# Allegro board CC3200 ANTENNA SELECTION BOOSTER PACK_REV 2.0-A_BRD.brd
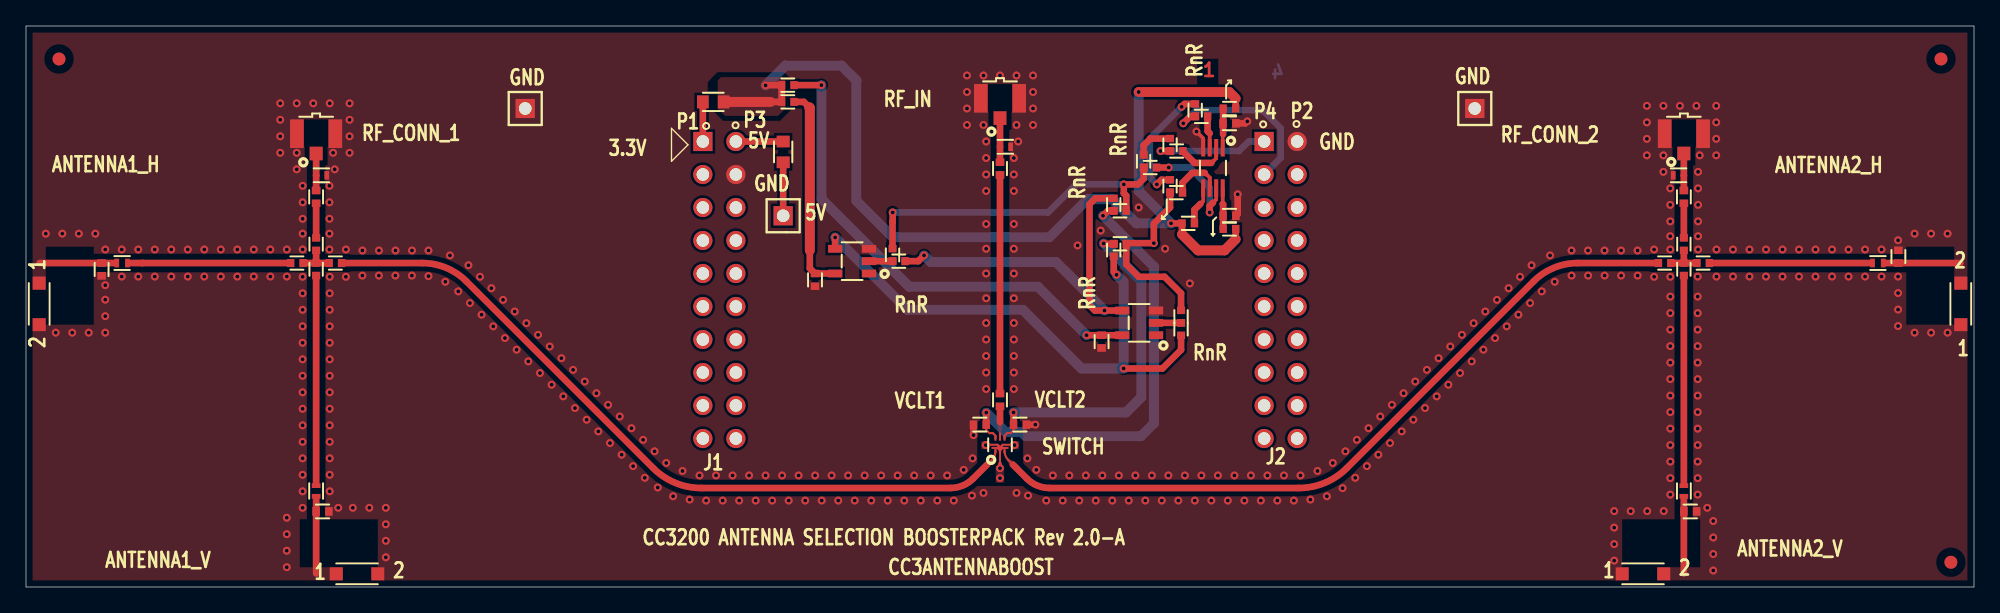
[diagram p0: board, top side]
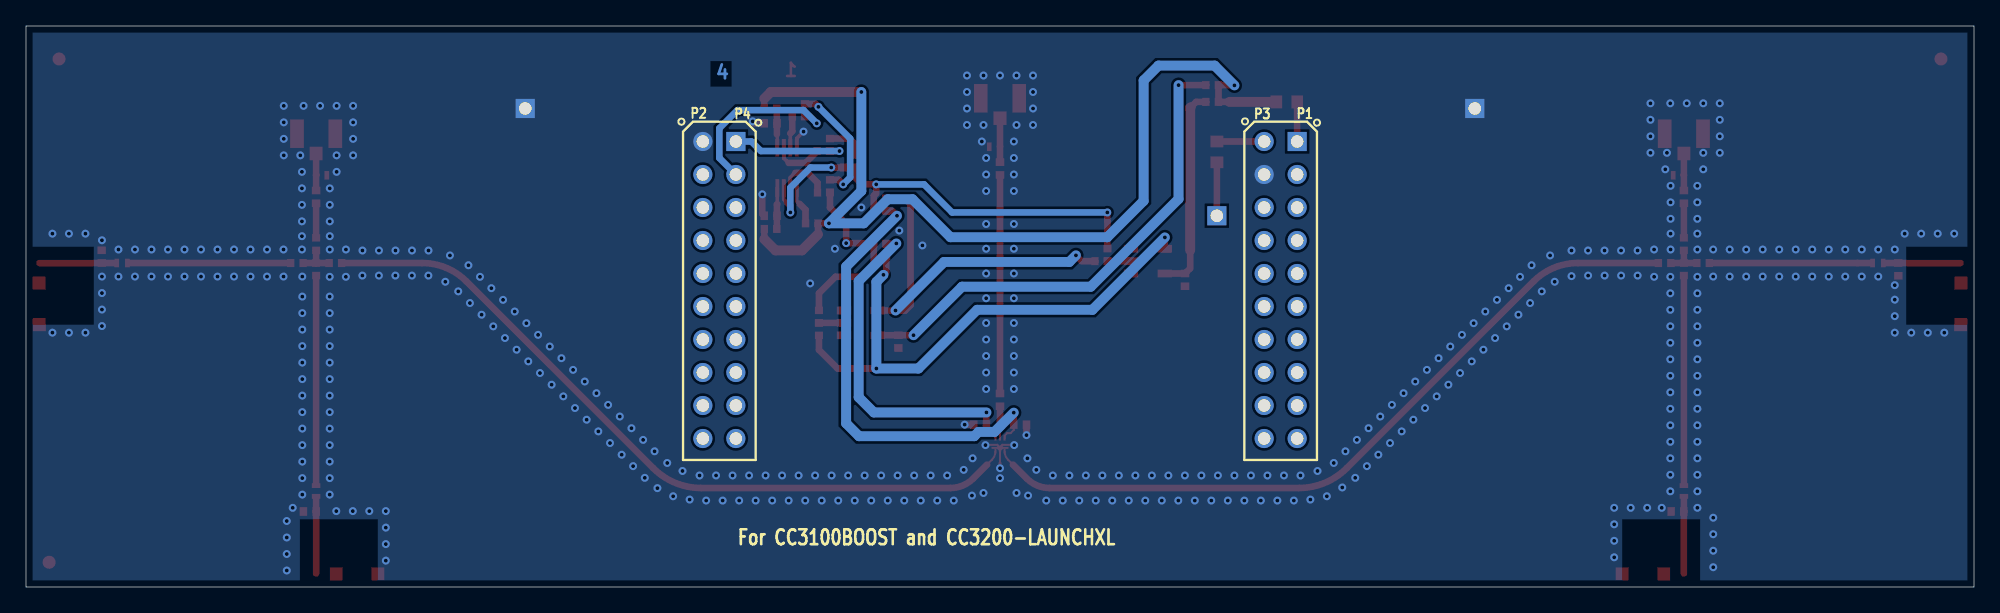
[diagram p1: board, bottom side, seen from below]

Outline 149.86 x 43.18 mm; copper layers: TOP, GND, PWR, BOTTOM. Coordinates in mm from the lower left corner of the outline.
Outline path: 0,43.18 149.86,43.18 149.86,0 0,0 0,43.18

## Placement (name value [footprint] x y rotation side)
C33  100pF  [CC0402]  22.32 30.03 90 top
C34  1pF  [CC0402]  22.81 5.82 180 top
C35  100pF  [CC0402]  127.54 30.03 90 top
C36  1pF  [CC0402]  128.03 5.82 180 top
C37  10pF  [CC0402]  74.93 32.21 90 top
C38  100pF  [CC0402]  74.93 14.4 90 top
C39  33pF  [CC0402]  76.46 12.5 0 top
C40  33pF  [CC0402]  73.38 12.5 180 top
C42  1pF  [CC0402]  144.04 25.43 270 top
C44  1pF  [CC0402]  5.82 24.45 90 top
C45  1uF  [CC0402]  60.7 23.64 270 top
C46  1uF  [CC0402]  82.75 18.89 270 top
C47  0.1uF  [CC0402]  92.58 35.69 0 top
C48  0.1uF  [CC0402]  92.58 28.57 0 top
E1  2.45GHz Ant  [ANT_AH316M]  25.47 1.02 0 top
E2  2.45GHz Ant  [ANT_AH316M]  124.39 1.02 0 top
E4  2.45GHz Ant  [ANT_AH316M]  148.84 21.79 90 top
E6  2.45GHz Ant  [ANT_AH316M]  1.02 21.79 270 top
J1  CONN_RCPT_10x2  [HDR_THVT_2X10_100_F]  52.07 34.29 180 bottom
J2  CONN_RCPT_10x2  [HDR_THVT_2X10_100_F]  95.25 34.29 180 bottom
J17  CONN_U.FL  [EMERSON_128-0711-201]  22.32 34.89 0 top
J18  CONN_U.FL  [EMERSON_128-0711-201]  127.54 34.89 0 top
J19  CONN_U.FL  [EMERSON_128-0711-201]  74.93 37.61 0 top
L7  NC  [INDC_0402CS]  22.73 31.69 180 top
L10  3.6nH  [INDC_0402CS]  22.32 7.39 270 top
L11  3.6nH  [INDC_0402CS]  127.54 7.39 270 top
L12  NC  [INDC_0402CS]  127.13 31.69 0 top
L13  NC  [INDC_0402CS]  75.34 33.88 180 top
L15  3.6nH  [INDC_0402CS]  142.47 24.94 0 top
L17  3.6nH  [INDC_0402CS]  7.39 24.94 180 top
NOREF  -  []  49.53 0 90 top
NOREF#2  -  []  23.79 34.89 0 top
NOREF#3  -  [unnamed#2]  147.32 40.64 0 top
NOREF#4  -  [unnamed#2]  148.08 1.91 0 top
NOREF#5  -  [unnamed#2]  2.54 40.64 0 top
NOREF#6  -  []  0 43.18 0 top
NOREF#7  -  []  27.07 1.02 0 top
R44  NC  [RC0402]  22.32 26.39 270 top
R45  0 R  [RC0402]  22.32 24.46 270 top
R46  NC  [RC0402]  127.54 26.39 270 top
R47  0 R  [RC0402]  127.54 24.46 270 top
R50  NC  [RC0402]  20.84 24.94 180 top
R59  RES0603  [RC0603]  52.87 37.34 180 top
R60  RES0603  [RC0603]  58.25 33.49 90 top
R62  0 R  [RC0402]  23.8 24.94 180 top
R64  0 R  [RC0402]  126.06 24.94 0 top
R73  0 R  [RC0402]  58.61 38.63 180 top
R74  0 R  [RC0402]  58.61 37.34 180 top
R76  NC  [RC0402]  129.02 24.94 0 top
R79  0 R  [RC0402]  89.41 27.99 0 top
R80  0 R  [RC0402]  92.58 36.83 0 top
R81  0 R  [RC0402]  92.58 27.56 0 top
R82  0 R  [RC0402]  88.52 33.56 180 top
R83  NC  [RC0402]  88.01 34.04 270 top
R85  NC  [RC0402]  89.94 36.7 270 top
R86  0 R  [RC0402]  90.42 36.22 0 top
R88  0 R  [RC0402]  86.49 32.29 180 top
R89  NC  [RC0402]  85.98 32.77 90 top
R90  0 R  [RC0402]  88.49 30.35 180 top
R91  NC  [RC0402]  88.01 30.86 90 top
R92  0 R  [RC0402]  84.16 28.96 0 top
R93  0 R  [RC0402]  84.16 26.42 0 top
R94  NC  [RC0402]  83.68 29.44 90 top
R95  NC  [RC0402]  83.68 25.94 90 top
R96  NC  [RC0402]  66.66 25.56 270 top
R97  NC  [RC0402]  67.14 25.08 0 top
R98  NC  [RC0402]  88.86 19.85 90 top
R99  NC  [RC0402]  88.86 20.81 90 top
TP9  TP THRU  [HDR_THVT_1X1_100_M]  58.25 28.57 0 top
TP10  TP THRU  [HDR_THVT_1X1_100_M]  111.46 36.83 0 top
TP11  TP THRU  [HDR_THVT_1X1_100_M]  38.4 36.83 0 top
U1  SWITCH  [SW_SKY13351-378LF]  74.93 10.95 90 top
U4  SN74AVCH2T45DCUR  [SOP50P310X90-8]  91.31 32.26 270 top
U6  INVERTER  [SOT23-5]  63.55 25.08 180 top
U7  INVERTER  [SOT23-5]  85.63 20.33 180 top

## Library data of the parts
C33-C40 C42 C44-C48 = CAP
E1 E2 E4 E6 = CHIP_ANTENNA_2T
J1 J2 = CONN_RCPT_10X2
J17-J19 = CONN_UFL_3P
L7 L10-L13 L15 L17 = INDUCTOR
R44-R47 R50 R62 R64 R73 R74 R76 R79-R83 R85 R86 R88-R99 = RESISTOR
R59 R60 = RES0603
TP9-TP11 = TEST_POINT_THRU
U1 = SWITCH
U4 = SN74AVCH2T45
U6 U7 = INVERTER

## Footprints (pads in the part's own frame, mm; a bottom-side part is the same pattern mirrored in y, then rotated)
ANT_AH316M
  rect 1x1 smd: 1(-1.6,0) 2(1.6,0)
CC0402
  rect 0.58x0.66 smd: 1(-0.49,0) 2(0.49,0)
EMERSON_128-0711-201
  rect 1x1.05 smd: 1(0,-1.525)
  rect 1.05x2.2 smd: 2A(-1.475,0) 2B(1.475,0)
HDR_THVT_1X1_100_M
  rect 1.473x1.473 hole 0.965: 1(0,0)
HDR_THVT_2X10_100_F
  rect 1.473x1.473 hole 0.965: 1(0,0)
  round 1.473 hole 0.965: 2(-2.54,0) 3(0,-2.54) 4(-2.54,-2.54) 5(0,-5.08) 6(-2.54,-5.08) 7(0,-7.62) 8(-2.54,-7.62) 9(0,-10.16) 10(-2.54,-10.16) 11(0,-12.7) 12(-2.54,-12.7) 13(0,-15.24) 14(-2.54,-15.24) 15(0,-17.78) 16(-2.54,-17.78) 17(0,-20.32) 18(-2.54,-20.32) 19(0,-22.86) 20(-2.54,-22.86)
INDC_0402CS
  rect 0.36x0.66 smd: 1(-0.41,0) 2(0.41,0)
RC0402
  rect 0.57x0.62 smd: 1(-0.48,0) 2(0.48,0)
RC0603
  rect 0.9x1 smd: 1(-0.8,0) 2(0.8,0)
SOP50P310X90-8
  rect 1.346x0.305 smd: 1(-1.55,0.75) 2(-1.55,0.25) 3(-1.55,-0.25) 4(-1.55,-0.75) 5(1.55,-0.75) 6(1.55,-0.25) 7(1.55,0.25) 8(1.55,0.75)
SOT23-5
  rect 1.1x0.6 smd: 1(-1.3,0.95) 2(-1.3,0) 3(-1.3,-0.95) 4(1.3,-0.95) 5(1.3,0.95)
SW_SKY13351-378LF
  rect 0.33x0.15 smd: 1(-0.485,0.35) 3(-0.485,-0.35) 4(0.485,-0.35) 5(0.485,0) 6(0.485,0.35)
  custom 0.196x0.196 smd: 2(-0.5,0)
unnamed#2
  round 1 smd: (0,0)

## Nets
GND: C34.1 C34.2 C36.1 C36.2 C39.2 C40.2 C42.1 C42.2 C44.1 C44.2 C45.2 C46.2 C47.2 C48.2 E1.1(FEED) E1.2 E2.1(FEED) E2.2 E4.1(FEED) E4.2 E6.1(FEED) E6.2 J1.4 J2.2 J17.2A(GND1) J17.2B(GND2) J18.2A(GND1) J18.2B(GND2) J19.2A(GND1) J19.2B(GND2) L7.1 L10.2 L11.2 L12.1 L13.1 L15.2 L17.2 TP10.1 TP11.1 U1.2(GND) U4.4(GND) U6.3(GND) U7.3(GND)
VCC_3V3: R59.1 R73.2 R74.2 R79.1 R80.2 R81.2
VCC_3V3_GPIO26: C45.1 R74.1 U6.5(VCC)
VCC_3V3_GPIO27: C46.1 R73.1 U7.5(VCC)
VCC_5V: J1.2 R60.2
GPIO26: J2.1 R82.2 R83.2
GPIO27: J2.3 R85.2 R86.1
VCTL1: C40.1 R92.1 R94.1 U1.6(VCTL1)
VCTL2: C39.1 R93.1 R95.2 U1.4(VCTL2)
N192262: J1.1 R59.2
N192340: R60.1 TP9.1
N199868: R44.2 R45.1 R50.1 R62.2
N199876: R62.1 U1.1(OUT1)
N199888: R64.1 U1.3(OUT2)
N199912: C38.1 U1.5(IN)
N200476: C37.2 J19.1(CENTER) L13.2
N200512: C37.1 C38.2
N201883: L10.1 R45.2
N202698: C33.2 J17.1(CENTER) L7.2
N202732: C33.1 R44.1
N202976: L17.1 R50.2
N204722: R46.2 R47.1 R64.2 R76.1
N204850: L11.1 R47.2
N204918: C35.2 J18.1(CENTER) L12.2
N204956: C35.1 R46.1
N204984: L15.1 R76.2
N222165: C47.1 R80.1 U4.1(VCCA)
N222453: R88.1 U4.7(B1)
N222461: R90.1 U4.6(B2)
N222517: C48.1 R81.1 U4.8(VCCB)
N223645: R86.2 U4.3(A2)
N225569: R83.1 R89.2
N225701: R88.2 R89.1 R92.2 R96.1
N229561: R82.1 U4.2(A1)
N229933: R85.1 R91.2
N229937: R90.2 R91.1 R93.2 R99.2
N231294: R94.2 R97.2 U7.4(OUT)
N231312: R95.1 R98.1 U6.4(OUT)
N231358: R98.2 R99.1 U7.2(IN)
N231374: R96.2 R97.1 U6.2(IN)
N231796: R79.2 U4.5(DIR)

Pads without a net: J1 3 5 6 7 8 9 10 11 12 13 14 15 16 17 18 19 20; J2 4 5 6 7 8 9 10 11 12 13 14 15 16 17 18 19 20; U6 1; U7 1

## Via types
v1: diameter 0.61, hole 0.305, TOP to BOTTOM, 451 vias

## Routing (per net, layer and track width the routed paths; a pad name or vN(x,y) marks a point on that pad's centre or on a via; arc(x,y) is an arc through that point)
GND: length 33.7
  TOP w0.152: 74.93,9.88 74.93,9.65 ; 74.93,9.88 74.93,9.88 74.93,9.65 ; 74.93,9.88 U1.2 74.93,10.74 ; 74.93,9.65 74.93,9.65 ; 74.93,9.65 74.93,9.53 74.93,9.53 74.93,9.65 ; v1(73.84,10.92) 73.86,10.95 74.75,10.95 74.93,10.77 74.93,10.74 ; v1(76.05,10.92) 76.02,10.95 75.13,10.95 74.93,10.74
  TOP w0.203: L17.2 6.87,24.94 ; L15.2 143.02,24.94 ; L11.2 127.54,6.86 ; L10.2 22.32,6.89
  TOP w0.254: v1(74.93,9.14) 74.93,9.53
  TOP w0.279: U4.4 90.56,34.53 v1(90.04,35.05)
  TOP w0.505: v1(93.22,30.23) 93.22,28.72 C48.2 ; C47.2 93.8,35.69 v1(93.95,35.84)
  TOP w0.508: 143.02,24.94 C42.2 148.82,24.94 ; 22.32,1.04 C34.2 22.32,6.89 ; 6.87,24.94 C44.2 1.04,24.94 ; 127.54,1.04 C36.2 127.54,6.86 ; v1(77.65,12.5) 77.65,12.5 C39.2 ; C40.2 v1(72.89,11.69)
  vias: v1(1.52,27.2) v1(2.29,19.58) v1(2.79,27.2) v1(3.56,19.58) v1(4.06,27.2) v1(4.83,19.58) v1(5.33,27.2) v1(6.1,25.98) v1(6.1,23.23) v1(6.1,22.12) v1(6.1,20.85) v1(6.1,19.58) v1(7.37,25.98) v1(7.37,23.89) v1(8.64,25.98) v1(8.64,23.89) v1(9.91,25.98) v1(9.91,23.89) v1(11.18,25.98) v1(11.18,23.89) v1(12.45,25.98) v1(12.45,23.89) v1(13.72,25.98) v1(13.72,23.89) v1(14.99,25.98) v1(14.99,23.89) v1(16.26,25.98) v1(16.26,23.89) v1(17.53,25.98) v1(17.53,23.89) v1(18.8,25.98) v1(18.8,23.89) v1(19.56,37.23) v1(19.56,35.96) v1(19.56,34.69) v1(19.56,33.42) v1(20.07,25.98) v1(20.07,23.89) v1(20.06,5.33) v1(20.06,4.06) v1(20.06,2.79) v1(20.06,1.52) v1(20.83,37.23) v1(20.83,33.42) v1(20.83,32.15) v1(21.29,30.88) v1(21.29,29.61) v1(21.29,28.34) v1(21.29,27.2) v1(21.29,25.98) v1(21.28,23.88) v1(21.28,22.61) v1(21.28,21.34) v1(21.28,20.07) v1(21.28,18.8) v1(21.28,17.53) v1(21.28,16.26) v1(21.28,14.99) v1(21.28,13.72) v1(21.28,12.45) v1(21.28,11.18) v1(21.28,9.91) v1(21.28,8.64) v1(21.28,7.37) v1(21.28,6.1) v1(22.1,37.23) v1(23.34,30.88) v1(23.34,29.61) v1(23.34,28.34) v1(23.34,27.2) v1(23.34,25.98) v1(23.37,37.23) v1(23.36,23.88) v1(23.36,22.61) v1(23.36,21.34) v1(23.36,20.07) v1(23.36,18.8) v1(23.36,17.53) v1(23.36,16.26) v1(23.36,14.99) v1(23.36,13.72) v1(23.36,12.45) v1(23.36,11.18) v1(23.36,9.91) v1(23.36,8.64) v1(23.36,7.37) v1(23.62,33.42) v1(23.75,32.15) v1(24.02,6.1) v1(24.61,25.98) v1(24.61,23.88) v1(24.89,37.23) v1(24.89,35.96) v1(24.89,34.69) v1(24.89,33.42) v1(25.14,6.1) v1(25.88,25.9) v1(25.88,23.97) v1(26.41,6.1) v1(27.15,23.97) v1(27.15,25.9) v1(27.68,6.1) v1(27.68,4.83) v1(27.68,3.56) v1(27.68,2.29) v1(28.42,25.9) v1(28.42,23.97) v1(29.69,25.9) v1(29.69,23.97) v1(30.96,25.9) v1(30.96,23.93) v1(32.26,23.5) v1(32.61,25.52) v1(33.25,22.75) v1(34.04,24.77) v1(34.15,21.86) v1(34.92,23.88) v1(35.05,20.96) v1(35.8,23) v1(35.95,20.06) v1(36.7,22.1) v1(36.84,19.16) v1(37.6,21.2) v1(37.74,18.26) v1(38.5,20.31) v1(38.64,17.37) v1(39.39,19.41) v1(39.54,16.47) v1(40.29,18.51) v1(40.44,15.57) v1(41.19,17.61) v1(41.33,14.67) v1(42.09,16.71) v1(42.23,13.77) v1(42.99,15.82) v1(43.13,12.88) v1(43.88,14.92) v1(44.03,11.98) v1(44.78,14.02) v1(44.93,11.08) v1(45.68,13.12) v1(45.82,10.18) v1(46.58,12.22) v1(46.7,9.3) v1(47.48,11.33) v1(47.6,8.4) v1(48.36,10.45) v1(48.6,7.66) v1(49.25,9.55) v1(49.78,6.99) v1(50.51,8.93) v1(51.05,6.73) v1(51.82,8.59) v1(52.32,6.65) v1(53.09,8.59) v1(53.59,6.65) v1(54.36,8.59) v1(54.86,6.65) v1(55.63,8.59) v1(56.13,6.65) v1(56.9,8.59) v1(57.4,6.65) v1(58.17,8.59) v1(58.67,6.65) v1(59.44,8.59) v1(59.94,6.65) v1(60.71,8.59) v1(61.21,6.65) v1(61.98,8.59) v1(62.48,6.65) v1(63.25,8.59) v1(63.75,6.65) v1(64.52,8.59) v1(65.02,6.65) v1(65.79,8.59) v1(66.29,6.65) v1(67.06,8.59) v1(67.56,6.65) v1(68.33,8.59) v1(68.83,6.65) v1(69.6,8.59) v1(70.1,6.65) v1(70.87,8.59) v1(71.37,6.65) v1(72.14,9.02) v1(72.39,39.37) v1(72.39,38.1) v1(72.39,36.83) v1(72.39,35.56) v1(72.82,9.91) v1(72.77,7.04) v1(73.66,39.37) v1(73.66,35.56) v1(73.66,7.24) v1(73.86,34.29) v1(73.86,33.02) v1(73.86,31.75) v1(73.86,30.48) v1(73.86,27.94) v1(73.86,26.04) v1(73.86,24.13) v1(73.86,22.23) v1(73.86,20.32) v1(73.86,19.05) v1(73.86,17.78) v1(73.86,16.51) v1(73.86,15.24) v1(74.93,39.37) v1(74.93,8.38) v1(76,33.02) v1(76,31.75) v1(76,30.48) v1(76,27.94) v1(76,26.04) v1(76,24.13) v1(76,22.23) v1(76,20.32) v1(76,19.05) v1(76,17.78) v1(76,16.51) v1(76,15.24) v1(76.2,39.37) v1(76.2,35.56) v1(76.2,7.24) v1(76.33,34.29) v1(77.04,9.91) v1(77.09,7.04) v1(77.47,39.37) v1(77.47,38.1) v1(77.47,36.83) v1(77.47,35.56) v1(77.72,9.02) v1(78.49,6.65) v1(78.99,8.59) v1(79.76,6.65) v1(80.26,8.59) v1(80.9,26.29) v1(81.03,6.65) v1(81.53,8.59) v1(82.3,6.65) v1(82.68,27.43) v1(82.8,8.59) v1(83.57,6.65) v1(84.07,8.59) v1(84.84,6.65) v1(85.34,8.59) v1(85.6,29.21) v1(86.11,6.65) v1(86.61,8.59) v1(87.38,6.65) v1(87.63,26.04) v1(87.88,8.59) v1(88.65,6.65) v1(89.15,8.59) v1(89.53,23.37) v1(89.92,6.65) v1(90.42,8.59) v1(91.19,6.65) v1(91.69,8.59) v1(92.46,6.65) v1(92.96,8.59) v1(93.73,6.65) v1(94.23,8.59) v1(95,6.65) v1(95.5,8.59) v1(96.27,6.65) v1(96.77,8.59) v1(97.54,6.65) v1(98.04,8.59) v1(98.81,6.73) v1(99.35,8.93) v1(100.08,6.99) v1(100.53,9.55) v1(101.28,7.61) v1(101.5,10.45) v1(102.26,8.4) v1(102.38,11.33) v1(103.16,9.3) v1(103.28,12.22) v1(104.04,10.18) v1(104.18,13.12) v1(104.93,11.08) v1(105.08,14.02) v1(105.83,11.98) v1(105.98,14.92) v1(106.73,12.88) v1(106.87,15.82) v1(107.63,13.77) v1(107.77,16.71) v1(108.53,14.67) v1(108.67,17.61) v1(109.42,15.57) v1(109.57,18.51) v1(110.32,16.47) v1(110.47,19.41) v1(111.22,17.37) v1(111.36,20.31) v1(112.12,18.26) v1(112.26,21.2) v1(113.02,19.16) v1(113.16,22.1) v1(113.91,20.06) v1(114.06,23) v1(114.81,20.96) v1(114.94,23.88) v1(115.71,21.86) v1(115.82,24.77) v1(116.61,22.75) v1(117.25,25.52) v1(117.6,23.5) v1(118.9,25.9) v1(118.9,23.97) v1(120.17,25.9) v1(120.17,23.97) v1(121.44,25.9) v1(121.44,23.97) v1(122.18,5.84) v1(122.18,4.57) v1(122.18,3.3) v1(122.18,2.03) v1(122.71,25.9) v1(122.71,23.97) v1(123.45,5.84) v1(123.98,25.9) v1(123.98,23.97) v1(124.7,37.03) v1(124.7,35.76) v1(124.7,34.49) v1(124.7,33.22) v1(124.72,5.84) v1(125.25,25.98) v1(125.25,23.88) v1(125.97,37.03) v1(125.97,33.22) v1(125.97,31.95) v1(125.99,5.84) v1(126.49,30.68) v1(126.49,29.41) v1(126.49,28.14) v1(126.49,27) v1(126.49,25.98) v1(126.5,23.88) v1(126.5,22.35) v1(126.5,21.08) v1(126.5,19.81) v1(126.5,18.54) v1(126.5,17.27) v1(126.5,16) v1(126.5,14.73) v1(126.5,13.46) v1(126.5,12.19) v1(126.5,10.92) v1(126.5,9.65) v1(126.5,8.38) v1(126.5,7.11) v1(127.24,37.03) v1(128.51,37.03) v1(128.63,31.95) v1(128.63,30.68) v1(128.63,29.41) v1(128.63,28.14) v1(128.63,27) v1(128.63,25.98) v1(128.61,23.89) v1(128.61,22.35) v1(128.61,21.08) v1(128.61,19.81) v1(128.61,18.54) v1(128.61,17.27) v1(128.61,16) v1(128.61,14.73) v1(128.61,13.46) v1(128.61,12.19) v1(128.61,10.92) v1(128.61,9.65) v1(128.61,8.38) v1(128.61,7.11) v1(128.76,33.22) v1(129.34,6.1) v1(129.8,5.08) v1(129.8,3.81) v1(129.8,2.54) v1(129.8,1.27) v1(130.03,37.03) v1(130.03,35.76) v1(130.03,34.49) v1(130.03,33.22) v1(130.05,25.98) v1(130.05,23.89) v1(131.32,25.98) v1(131.32,23.89) v1(132.59,25.98) v1(132.59,23.89) v1(133.86,25.98) v1(133.86,23.89) v1(135.13,25.98) v1(135.13,23.89) v1(136.4,25.98) v1(136.4,23.89) v1(137.67,25.98) v1(137.67,23.89) v1(138.94,25.98) v1(138.94,23.89) v1(140.21,25.98) v1(140.21,23.89) v1(141.48,25.98) v1(141.48,23.89) v1(142.75,25.98) v1(142.75,23.89) v1(144.02,26.69) v1(144.02,23.89) v1(144.02,22.62) v1(144.02,21.35) v1(144.02,20.08) v1(145.29,27.2) v1(145.29,19.58) v1(146.56,27.2) v1(146.56,19.58) v1(147.83,27.2) v1(147.83,19.58)
VCC_3V3: length 78.8
  TOP w0.505: R73.2 56.88,38.63 v1(56.9,38.61) ; 88.93,27.15 R79.1 v1(88.09,27.99) ; R81.2 93.06,26.77 ; R80.2 93.06,37.6
  TOP w0.508: 57.28,37.34 R74.2 R73.2
  TOP w0.762: 88.93,27.15 90.17,25.91 92.2,25.91 93.06,26.77 ; 57.28,37.34 R59.1 ; 93.06,37.6 92.56,38.1 v1(85.6,38.1)
  BOTTOM w0.762: v1(85.6,38.1) 85.6,30.48 v1(88.09,27.99) 85.42,27.99 83.57,29.84 81.66,29.84 78.74,26.92 66.67,26.92 63.88,29.72 63.88,38.99 62.74,40.13 58.42,40.13 v1(56.9,38.61)
VCC_3V3_GPIO26: length 15.9
  TOP w0.505: 60.3,25.91 60.3,24.53 C45.1 U6.5 ; R74.1 59.84,37.34 60.24,36.94
  TOP w0.762: 60.3,25.91 60.3,36.88 60.24,36.94
VCC_3V3_GPIO27: length 38.4
  TOP w0.505: U7.5 C46.1 v1(81.58,19.38) ; R73.1 v1(61.19,38.63)
  BOTTOM w0.762: v1(81.58,19.38) 77.85,23.11 67.94,23.11 61.19,29.87 v1(61.19,38.63)
VCC_5V: length 3.6
  TOP w0.505: R60.2 J1.2
GPIO26: length 9
  TOP w0.508: R82.2 R83.2 v1(87.28,33.56)
  BOTTOM w0.505: J2.1 94.06,34.29 93.32,33.56 v1(87.28,33.56)
GPIO27: length 13.7
  TOP w0.505: v1(89.03,35.69) 89.56,36.22 R85.2
  BOTTOM w0.505: v1(89.03,35.69) 90.04,36.7 95.12,36.7 96.52,35.31 96.52,33.02 J2.3
VCTL1: length 35.1
  TOP w0.152: C40.1 73.87,12.08 74.11,11.84 74.38,11.84 74.58,11.64 U1.6
  TOP w0.505: R92.1 83.24,28.96 v1(82.85,28.57)
  TOP w0.508: C40.1 v1(73.87,13.42)
  BOTTOM w0.762: v1(73.87,13.42) 75.35,11.94 76.58,11.94 76.91,11.61 85.78,11.61 86.77,12.6 86.77,24.66 v1(82.85,28.57)
VCTL2: length 26.6
  TOP w0.152: U1.4 75.28,11.64 75.48,11.84 75.75,11.84 75.97,12.07 C39.1
  TOP w0.505: v1(82.91,26.44) 82.93,26.42 R93.1
  TOP w0.508: C39.1 v1(75.97,13.44)
  BOTTOM w0.762: v1(82.91,26.44) 85.8,23.55 85.8,14.61 84.63,13.44 v1(75.97,13.44)
N192262: length 3
  TOP w0.505: R59.2 J1.1
N192340: length 4.1
  TOP w0.505: TP9.1 R60.1
N199868: length 3
  TOP w0.508: R45.1 R50.1 ; R45.1 R62.2 ; R45.1 R44.2
N199876: length 58.3
  TOP w0.152: 73.94,9.42 74.3,9.78 arc(74.51,10.09) U1.1
  TOP w0.508: R62.1 30.48,24.94 arc(32.32,24.57) 33.87,23.53 48.26,9.14 arc(49.95,8.02) 51.94,7.62 71.12,7.62 arc(72.06,7.81) 72.85,8.34 73.94,9.42
N199888: length 58.3
  TOP w0.152: 75.92,9.42 75.56,9.78 arc(75.35,10.09) U1.3
  TOP w0.508: R64.1 119.38,24.94 arc(117.54,24.57) 115.99,23.53 101.6,9.14 arc(99.91,8.02) 97.92,7.62 78.74,7.62 arc(77.8,7.81) 77.01,8.34 75.92,9.42
N199912: length 1.6
  TOP w0.152: U1.5 74.93,11.82 74.93,11.83
  TOP w0.508: 74.93,12.7 C38.1
N200476: length 3.4
  TOP w0.508: C37.2 L13.2 J19.1
N200512: length 16.8
  TOP w0.508: C38.2 C37.1
N201883: length 16.2
  TOP w0.203: L10.1 22.32,7.9
  TOP w0.508: 22.32,7.9 R45.2
N202698: length 2.9
  TOP w0.508: J17.1 L7.2 C33.2
N202732: length 2.7
  TOP w0.508: C33.1 R44.1
N202976: length 12.6
  TOP w0.203: L17.1 7.94,24.94
  TOP w0.508: R50.2 8.95,24.94 7.94,24.94
N204722: length 3
  TOP w0.508: R47.1 R64.2 ; R47.1 R46.2 ; R47.1 R76.1
N204850: length 16.2
  TOP w0.203: L11.1 127.54,7.95
  TOP w0.508: 127.54,7.95 R47.2
N204918: length 2.9
  TOP w0.508: J18.1 L12.2 C35.2
N204956: length 2.7
  TOP w0.508: R46.1 C35.1
N204984: length 12.6
  TOP w0.203: L15.1 141.92,24.94
  TOP w0.508: 141.92,24.94 R76.2
N222165: length 3
  TOP w0.254: 92.09,34.84 92.06,34.81 U4.1
  TOP w0.505: 92.09,34.84 C47.1 92.09,36.82 R80.1
N222453: length 8.7
  TOP w0.279: 91.31,29.58 91.56,29.83 U4.7
  TOP w0.505: R88.1 v1(87.91,32.29) ; 91.31,29.58 91.06,29.32 v1(91.06,28.83)
  BOTTOM w0.505: v1(87.91,32.29) 89.51,32.29 91.06,30.73 v1(91.06,28.83)
N222461: length 4.1
  TOP w0.279: U4.6 91.06,31.49 91.06,31.5 91.06,31.52 90.86,31.72 90.83,31.72 90.68,31.88
  TOP w0.505: R90.1 88.97,31.12 89.73,31.88 90.68,31.88
N222517: length 3.2
  TOP w0.279: 92.06,29.48 U4.8
  TOP w0.505: 92.06,29.48 92.09,29.45 C48.1 92.09,27.57 R81.1
N223645: length 2.5
  TOP w0.279: 91.06,34.92 U4.3
  TOP w0.505: R86.2 90.9,35.08 91.06,34.92
N225569: length 3
  TOP w0.508: R83.1 86.51,34.52 85.98,33.99 R89.2
N225701: length 26.1
  TOP w0.505: v1(66.67,28.83) 66.67,28.14 66.66,28.13 R96.1 ; R92.2 84.64,30.12 84.45,30.3 v1(84.45,30.99) 85.54,30.99 85.98,31.43 R89.1
  BOTTOM w0.505: v1(66.67,28.83) 78.61,28.83 80.77,30.99 v1(84.45,30.99)
N229561: length 3.9
  TOP w0.203: 89,33.53 R82.1
  TOP w0.279: 91.19,32.64 91.34,32.79 91.36,32.79 91.56,32.99 91.56,33.01 91.56,33.02 U4.2
  TOP w0.505: 89,33.53 89.89,32.64 91.19,32.64
N229933: length 9.5
  TOP w0.505: R91.2 87.35,31.34 v1(87,30.99) ; R85.1 89.13,37.18 v1(88.9,36.96)
  BOTTOM w0.505: v1(87,30.99) 86.46,31.53 86.46,34.51 v1(88.9,36.96)
N229937: length 14.6
  TOP w0.505: R91.1 R90.2 88.01,29.21 86.77,27.97 v1(86.77,26.47) 84.69,26.47 R93.2 84.64,24.83 85.6,23.88 87.59,23.88 88.86,22.61 R99.2
N231294: length 29.8
  TOP w0.505: v1(69.09,25.53) 68.64,25.08 R97.2 ; R94.2 82.27,29.92 81.81,29.46 81.81,21.69 82.22,21.28 v1(82.97,21.28) U7.4
  BOTTOM w0.762: v1(69.09,25.53) 69.6,25.02 79.23,25.02 v1(82.97,21.28)
N231312: length 42.3
  TOP w0.505: R95.1 83.68,24.24 v1(83.9,24.03) ; U6.4 62.25,26.04 v1(62.25,26.91) ; v1(84.44,16.82) 87.42,16.82 88.86,18.25 R98.1
  BOTTOM w0.762: v1(83.9,24.03) 84.44,23.48 v1(84.44,16.82) 81.2,16.82 76.69,21.34 67.82,21.34 v1(62.25,26.91)
N231358: length 1.9
  TOP w0.505: R98.2 U7.2
N231374: length 1.8
  TOP w0.505: U6.2 R97.1
N231796: length 3
  TOP w0.279: 90.35,29.49 90.35,29.5 90.56,29.69 U4.5
  TOP w0.505: 90.35,29.49 89.89,29.03 R79.2

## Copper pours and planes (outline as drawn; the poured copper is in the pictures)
GND on TOP: 19,0.51 0.51,0.51 0.51,17.63 0.51,28.45 0.51,42.67 149.35,42.67 149.35,27.05 149.35,18.72 149.35,0.51 129.54,0.51 120.29,0.51 29.72,0.51 ; 10 cut-outs
GND on BOTTOM: 0.51,0.51 0.51,17.63 0.51,20.19 5.22,20.19 5.22,26.19 0.51,26.19 0.51,42.67 149.35,42.67 149.35,27.86 149.35,26.19 144.64,26.19 144.64,20.19 149.35,20.19 149.35,0.51 129.54,0.51 128.79,0.51 128.79,5.22 122.79,5.22 122.79,0.51 29.72,0.51 27.07,0.51 27.07,5.22 21.07,5.22 21.07,0.51
GND on GND, PWR: 19,0.51 0.51,0.51 0.51,17.63 0.51,28.45 0.51,42.67 149.35,42.67 149.35,27.86 149.35,18.72 149.35,0.51 129.54,0.51 120.29,0.51 29.72,0.51
VCC_3V3 on TOP: 57.85,36.26 58.42,36.83 58.42,38.99 58.17,39.24 53.47,39.24 53.21,38.99 53.21,36.83 53.78,36.26
N199876 on TOP: 74.32,9.92 74.32,9.92 74.43,9.83 74.43,9.8 74.14,9.28 74.04,9.17 73.73,8.85 73.37,9.2 73.78,9.61
N199888 on TOP: 75.52,9.94 75.51,9.94 75.41,9.86 75.41,9.83 75.69,9.3 75.79,9.2 76.11,8.88 76.47,9.23 76.06,9.64

Small or netless copper shapes (teardrops, artwork), in the pictures only: 4 on TOP

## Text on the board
BOTTOM: 4
Ref Des/Assembly Bottom: P1 | P3 | P4 | P2
Ref Des/Silkscreen Bottom: P1 | P3 | P4 | P2 | For CC3100BOOST and CC3200-LAUNCHXL
User.Comments: UNLESS OTHERWISE SPECIFIED | ALL DIMENSIONS ARE IN | INCHES | MILLIMETERS | REV 2.0-A | MAY 30 2014 | DATE | PART NUMBER: | CC3200 ANTENNA SELECTION BOOSTERPACK | A | FABRICATION DRAWING | TEXAS INSTRUMENTS | X
TOP: 1
Ref Des/Assembly Top: 1 | 2
Ref Des/Silkscreen Top: ANTENNA1_H | ANTENNA1_V | 1 | RF_CONN_1 | 2 | GND | 3.3V | CC3200 ANTENNA SELECTION BOOSTERPACK Rev 2.0-A | P1 | J1 | P3 | 5V | RF_IN | CC3ANTENNABOOST | RnR | VCLT1 | VCLT2 | SWITCH | P4 | J2 | P2 | RF_CONN_2 | ANTENNA2_V | ANTENNA2_H
GND: 2
PWR: 3
PAGE_OUTLINE: NOTES: UNLESS OTHERWISE SPECIFIED. | 9. MINIMUM CONDUCTOR WIDTH:4.0 MILS | REQUIREMENTS. | COPPER: AS PER STACKUP. | DIELECTRIC: FR4 | U.L. RATING: 94V-0 MINIMUM | 11.12MIL VIAS ARE TENTED IN BOTH THE MASK LAYER. | 1. FABRICATE PER IPC-6012A CLASS 2. | 2. SURFACE FINISH:  ENIG | 5. 100% CONTINUITY TESTING USING DATABASE NETLIST SHALL BE PERFORMED, | VENDOR TO IDENTIFY TEST PASSED IN SECONDARY  SIDE. | 3. SOLDER MASK MATERIAL SHALL MEET ALL THE REQUIREMENTS OF | IPC-SM-840C AND SHALL BE GREEN IN COLOR AND APPLIED OVER BARE COPPER. | 6. VENDOR TO MARK DATE CODE AND LOGO  IN ETCH OR IN LEGEND. | 10.SOLDER MASK CLEARANCE IS GIVEN SAME AS PAD SIZE EXCEPT NPTH AND FIDUCIALS. | 4. SILK SCREEN LEGEND TO BE APPLIED PER LAYER STACKUP USING WHITE | NON-CONDUCTIVE EPOXY INK. | 12.0.0121" VIAS ARE TO BE FILLED WITH NON-CONDUCTIVE EPOXY(VENDOR CHOICE) AND PLATED | 8. DIELECTRICS AND LINEWIDTHS MAY BE ADJUSTED TO MEET THE IMPEDANCE | 7. BOW AND TWIST SHALL NOT EXCEED 0.7% OF LONGEST SIDE . | VENDER SHALL MODIFY THE MASK CLEARANCE AS PER THE REQUIRED MANUFACTURING TOLERANCE. | +0.000"/-0.001" ON TOP SIDE AND +0.000"/-0.003" ON THE BOTTOM SIDE. | OVER WITH COPPER NICKEL AND GOLD. SURFACE MUST BE FLAT. FLATNESS TOLERANCE IS | MINIMUM SPACING:4.0 MILS | 60.85 Mils+/-10% | 6-LAYER STACK BUILD | SECONDARY SIDE, SOLDER MASK | SECONDARY SIDE, SILK SCREEN | GROUND2     , LAYER 5   ----->1.378 Mils | DIELECTRIC              ----->3.70  Mils | SECONDARY SIDE,LAYER 6  ----->1.969 Mils | PRIMARY SIDE, SILK SCREEN | PRIMARY SIDE, SOLDER MASK | PRIMARY SIDE, LAYER 1   ----->1.969 Mils | GROUND1     , LAYER 2   ----->1.378 Mils | DIELECTRIC              ----->6.00  Mils | CAD | DATA | DO NOT MANUALLY | UPDATE | D | C | B | A | 8 | 7 | 6 | 5 | 4 | 3 | 2 | 1
User.5: FABRICATION DRAWING | LAYER NO | 1 | CONDUCTOR WIDTH | 20.0 MIL | SINGLE ENDED IMPEDANCE | REFERENCE LAYER | 2 | IMPEDANCE +/- 10% | 50 OHMS
User.6: DATE:MAY 30 2014 | PART NO/CARD REF: | FILM LAYER: | TESSOLVE | CC3200 ANTENNA SELECTION BOOSTERPACK | JOB NUMBER:TS10043 | REV 2.0-A | DESIGNED BY: | COMPANY NAME : TEXAS INSTRUMENTS
User.7: PRIMARY SIDE
User.8: LAYER 2 (GND)
User.9: LAYER 3 (GND)
User.12: LAYER 4(BOTTOM SIDE)"
User.13: PRIMARY SIDE SILKSCREEN
User.14: SECONDARY SIDE  SILKSCREEN
User.15: PRIMARY SIDE PASTE LAYER
User.16: SECONDARY SIDE PASTE LAYER
User.17: PRIMARY SIDE SOLDERMASK
User.18: SECONDARY SIDE SOLDERMASK
User.19: OUTLINE
User.21: ASSEMBLY PRIMARY SIDE
User.22: ASSEMBLY SECONDARY SIDE
User.23: 5.   ALL VIAS TO BE TENTED. | GENERAL NOTES-- UNLESS OTHERWISE SPECIFIED: | 1.   FABRICATE PER IPC-6012A CLASS 2 | 2.   SURFACE FINISH   :  ENIG | 3.   MATERIAL; FR4 | 4.   COPPER WT: 1 Oz | BOARD THICKNESS : 1.2 mm(+/- 0.1mm) | 6.   SOLDER MASK CLEARANCE IS GIVEN | 7. SOLDER MASK COLOUR : RED | 8. SILKSCREEN COLOUR : WHITE | SAME AS PAD SIZE EXCEPT FIDUCIAL | VENDOR SHALL MODIFY THE MASK CLEARANCE AS PER | THE REQUIRED MANUFACTURING TOLERANCE | STACK UP | NO SCALE | SECTION A-A | LAYER 03 - GND PLANE | LAYER 01-TOP SIDE | LAYER 02 - GND PLANE | LAYER 04 - BOTTOM
User.25: FIGURE | SIZE | 12.0 | 38.0 | DRILL CHART: TOP to BOTTOM | ALL UNITS ARE IN MILS | TOLERANCE | +0.0/-12.0 | +3.0/-3.0 | PLATED | QTY | 451 | 43
